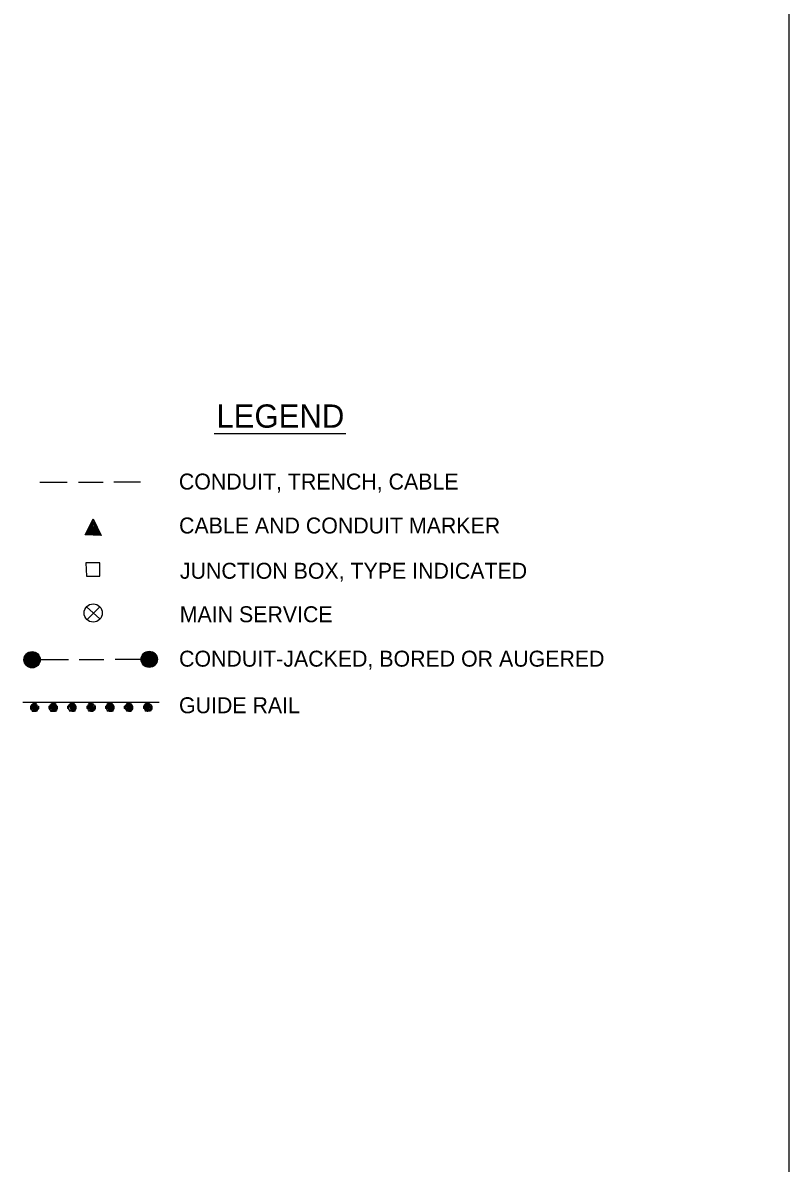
# Model space of a CAD drawing. Extents: x 36 to 2622, y -5330 to 219.
# Drawn here: x 717.9 to 861.9, y -5154 to -4939.9 of the extents above; entities that cross this region are included whole.
import ezdxf

# ---------------------------------------------------------------- set-up
doc = ezdxf.new("R2010")
doc.units = 0
doc.layers.add('1', color=7, linetype='Continuous')
doc.layers.add('2', color=7, linetype='Continuous')

msp = doc.modelspace()

# ---------------------------------------------------------------- linework, layer by layer
at = {"layer": '1'}
msp.add_line((861.86, -5314.83), (861.86, -4750.83), dxfattribs=at)
at = {"layer": '2'}
for p, q in [((753.84, -5017), (778.59, -5017)), ((721.13, -5026.13), (726.25, -5026.13)), ((728.38, -5026.13), (733, -5026.13)), ((740, -5026.13), (735, -5026.13)), ((729.63, -5036), (731.13, -5033)), ((729.75, -5036), (731.13, -5033.25)), ((729.88, -5035.88), (731.13, -5033.5)), ((731.13, -5033), (732.63, -5036.13)), ((731.13, -5033.25), (732.5, -5036)), ((731.13, -5033.5), (732.38, -5035.88)), ((730.13, -5035.75), (731.13, -5033.63)), ((730.25, -5035.63), (731.13, -5033.88)), ((731.88, -5035.63), (730.25, -5035.63)), ((730.38, -5035.38), (731.13, -5034.25)), ((731.75, -5035.38), (730.38, -5035.38)), ((730.5, -5035.38), (731.13, -5034.5)), ((731.5, -5035.38), (730.5, -5035.38)), ((730.88, -5035.25), (731.13, -5034.63)), ((731.38, -5035.25), (730.88, -5035.25)), ((731, -5035.13), (731.13, -5034.88)), ((731.25, -5035.13), (731, -5035.13)), ((731.13, -5033.63), (732, -5035.75)), ((731.13, -5033.88), (731.88, -5035.63)), ((731.13, -5034.25), (731.75, -5035.38)), ((731.13, -5034.5), (731.5, -5035.38)), ((731.13, -5034.63), (731.38, -5035.25)), ((731.13, -5034.88), (731.25, -5035.13)), ((732.63, -5036.13), (729.63, -5036)), ((732.5, -5036), (729.75, -5036)), ((732.38, -5035.88), (729.88, -5035.88)), ((732, -5035.75), (730.13, -5035.75)), ((729.88, -5049.5), (732.38, -5051.75)), ((732.38, -5049.5), (730, -5051.88)), ((721.25, -5059.38), (726.5, -5059.38)), ((728.5, -5059.38), (733.13, -5059.38)), ((740.13, -5059.38), (735.25, -5059.38)), ((717.91, -5067.45), (743.52, -5067.45)), ((720.14, -5068.2), (720.14, -5068.2)), ((723.64, -5068.2), (723.64, -5068.2)), ((727.26, -5068.2), (727.26, -5068.2)), ((730.76, -5068.2), (730.76, -5068.2)), ((734.39, -5068.2), (734.39, -5068.2)), ((737.89, -5068.2), (737.89, -5068.2)), ((741.39, -5068.2), (741.39, -5068.2))]:
    msp.add_line(p, q, dxfattribs=at)
msp.add_lwpolyline([(729.88, -5043.75), (732.38, -5043.75), (732.38, -5041.25), (729.75, -5041.25)], close=True, dxfattribs=at)
for points in [[(720.14, -5068.45), (720.01, -5068.45), (720.01, -5068.45), (720.14, -5068.2), (720.26, -5068.45), (720.14, -5068.58), (720.01, -5068.7), (719.89, -5068.58), (719.89, -5068.45), (719.89, -5068.2), (720.01, -5068.08), (720.26, -5068.08), (720.39, -5068.45), (720.39, -5068.58), (720.14, -5068.83), (719.89, -5068.7), (719.76, -5068.58), (719.76, -5068.2), (719.89, -5067.95), (720.26, -5067.95), (720.39, -5068.08), (720.51, -5068.45), (720.51, -5068.7), (720.26, -5068.83), (720.14, -5068.95), (719.89, -5068.95), (719.64, -5068.83), (719.51, -5068.58), (719.64, -5068.2), (719.76, -5067.95), (720.01, -5067.83), (720.39, -5067.83), (720.51, -5068.08), (720.64, -5068.45), (720.64, -5068.7), (720.51, -5068.95), (720.26, -5069.08), (720.01, -5069.08), (719.76, -5069.08), (719.64, -5068.95), (719.51, -5068.83), (719.39, -5068.58), (719.39, -5068.2), (719.51, -5068.08), (719.64, -5067.83), (719.89, -5067.7), (720.01, -5067.7), (720.26, -5067.7), (720.39, -5067.7), (720.51, -5067.83), (720.64, -5068.08), (720.89, -5068.2), (720.89, -5068.58), (720.89, -5068.7), (720.64, -5068.95), (720.51, -5069.08), (720.39, -5069.2), (720.14, -5069.2), (720.01, -5069.2), (719.76, -5069.2), (719.64, -5069.08)], [(723.64, -5068.45), (723.51, -5068.45), (723.51, -5068.45), (723.64, -5068.2), (723.89, -5068.45), (723.64, -5068.58), (723.51, -5068.7), (723.39, -5068.58), (723.39, -5068.45), (723.39, -5068.2), (723.51, -5068.08), (723.89, -5068.08), (724.01, -5068.45), (724.01, -5068.58), (723.64, -5068.83), (723.39, -5068.7), (723.26, -5068.58), (723.26, -5068.2), (723.39, -5067.95), (723.89, -5067.95), (724.01, -5068.08), (724.14, -5068.45), (724.14, -5068.7), (723.89, -5068.83), (723.64, -5068.95), (723.39, -5068.95), (723.14, -5068.83), (723.01, -5068.58), (723.14, -5068.2), (723.26, -5067.95), (723.51, -5067.83), (724.01, -5067.83), (724.14, -5068.08), (724.26, -5068.45), (724.26, -5068.7), (724.14, -5068.95), (723.89, -5069.08), (723.51, -5069.08), (723.26, -5069.08), (723.14, -5068.95), (723.01, -5068.83), (722.89, -5068.58), (722.89, -5068.2), (723.01, -5068.08), (723.14, -5067.83), (723.39, -5067.7), (723.51, -5067.7), (723.89, -5067.7), (724.01, -5067.7), (724.14, -5067.83), (724.26, -5068.08), (724.39, -5068.2), (724.39, -5068.58), (724.39, -5068.7), (724.26, -5068.95), (724.14, -5069.08), (724.01, -5069.2), (723.64, -5069.2), (723.51, -5069.2), (723.26, -5069.2), (723.14, -5069.08)], [(727.26, -5068.45), (727.14, -5068.45), (727.14, -5068.2), (727.26, -5068.2), (727.39, -5068.45), (727.26, -5068.58), (727.14, -5068.7), (727.01, -5068.58), (727.01, -5068.45), (727.01, -5068.2), (727.14, -5068.08), (727.39, -5068.08), (727.51, -5068.45), (727.51, -5068.58), (727.26, -5068.83), (727.01, -5068.7), (726.89, -5068.58), (726.89, -5068.2), (727.01, -5067.95), (727.39, -5067.95), (727.51, -5068.08), (727.64, -5068.45), (727.64, -5068.7), (727.39, -5068.83), (727.26, -5068.95), (727.01, -5068.95), (726.64, -5068.83), (726.51, -5068.58), (726.64, -5068.2), (726.89, -5067.95), (727.14, -5067.83), (727.51, -5067.83), (727.64, -5068.08), (727.76, -5068.2), (727.76, -5068.7), (727.64, -5068.95), (727.39, -5069.08), (727.14, -5069.08), (726.89, -5069.08), (726.64, -5068.95), (726.51, -5068.7), (726.39, -5068.58), (726.39, -5068.2), (726.51, -5068.08), (726.64, -5067.83), (726.89, -5067.7), (727.14, -5067.7), (727.39, -5067.7), (727.51, -5067.7), (727.64, -5067.83), (727.76, -5067.95), (727.89, -5068.2), (727.89, -5068.58), (727.89, -5068.7), (727.76, -5068.95), (727.64, -5069.08), (727.51, -5069.2), (727.26, -5069.2), (727.14, -5069.2), (726.89, -5069.08), (726.64, -5069.08)], [(730.76, -5068.45), (730.64, -5068.45), (730.64, -5068.2), (730.76, -5068.2), (730.89, -5068.45), (730.76, -5068.58), (730.64, -5068.7), (730.51, -5068.58), (730.51, -5068.45), (730.51, -5068.2), (730.64, -5068.08), (730.89, -5068.08), (731.01, -5068.45), (731.01, -5068.58), (730.76, -5068.83), (730.51, -5068.7), (730.39, -5068.58), (730.39, -5068.2), (730.51, -5067.95), (730.89, -5067.95), (731.01, -5068.08), (731.14, -5068.45), (731.14, -5068.7), (730.89, -5068.83), (730.76, -5068.95), (730.51, -5068.95), (730.26, -5068.83), (730.14, -5068.58), (730.26, -5068.2), (730.39, -5067.95), (730.64, -5067.83), (731.01, -5067.83), (731.14, -5068.08), (731.39, -5068.2), (731.39, -5068.7), (731.14, -5068.95), (730.89, -5069.08), (730.64, -5069.08), (730.39, -5069.08), (730.26, -5068.95), (730.14, -5068.7), (730.01, -5068.58), (730.01, -5068.2), (730.14, -5068.08), (730.26, -5067.83), (730.39, -5067.7), (730.64, -5067.7), (730.89, -5067.7), (731.01, -5067.7), (731.14, -5067.83), (731.39, -5067.95), (731.51, -5068.2), (731.51, -5068.58), (731.51, -5068.7), (731.39, -5068.95), (731.14, -5069.08), (731.01, -5069.2), (730.76, -5069.2), (730.64, -5069.2), (730.39, -5069.08), (730.26, -5069.08)], [(734.39, -5068.45), (734.14, -5068.45), (734.14, -5068.2), (734.39, -5068.2), (734.51, -5068.45), (734.39, -5068.58), (734.14, -5068.7), (734.01, -5068.58), (734.01, -5068.45), (734.01, -5068.2), (734.14, -5068.08), (734.51, -5068.08), (734.64, -5068.45), (734.51, -5068.58), (734.39, -5068.83), (734.01, -5068.7), (733.89, -5068.58), (733.89, -5068.08), (734.01, -5067.95), (734.51, -5067.95), (734.64, -5068.08), (734.76, -5068.45), (734.76, -5068.7), (734.51, -5068.83), (734.39, -5068.95), (734.01, -5068.95), (733.76, -5068.83), (733.64, -5068.58), (733.76, -5068.2), (733.89, -5067.95), (734.14, -5067.83), (734.64, -5067.83), (734.76, -5068.08), (734.89, -5068.2), (734.89, -5068.7), (734.76, -5068.95), (734.51, -5069.08), (734.14, -5069.08), (733.89, -5069.08), (733.76, -5068.95), (733.64, -5068.7), (733.51, -5068.58), (733.51, -5068.2), (733.64, -5068.08), (733.76, -5067.83), (733.89, -5067.7), (734.14, -5067.7), (734.51, -5067.7), (734.64, -5067.7), (734.76, -5067.83), (734.89, -5067.95), (735.01, -5068.2), (735.01, -5068.58), (735.01, -5068.7), (734.89, -5068.95), (734.76, -5069.08), (734.64, -5069.2), (734.39, -5069.2), (734.14, -5069.2), (733.89, -5069.08), (733.76, -5069.08)], [(737.89, -5068.45), (737.76, -5068.45), (737.76, -5068.2), (737.89, -5068.2), (738.01, -5068.45), (737.89, -5068.58), (737.76, -5068.58), (737.64, -5068.58), (737.64, -5068.45), (737.64, -5068.2), (737.76, -5068.08), (738.01, -5068.08), (738.14, -5068.45), (738.01, -5068.58), (737.89, -5068.83), (737.64, -5068.7), (737.51, -5068.58), (737.51, -5068.08), (737.64, -5067.95), (738.01, -5067.95), (738.14, -5068.08), (738.26, -5068.45), (738.26, -5068.7), (738.01, -5068.83), (737.89, -5068.95), (737.64, -5068.95), (737.39, -5068.7), (737.14, -5068.45), (737.39, -5068.2), (737.51, -5067.95), (737.76, -5067.83), (738.14, -5067.83), (738.26, -5068.08), (738.39, -5068.2), (738.39, -5068.7), (738.26, -5068.95), (738.01, -5069.08), (737.76, -5069.08), (737.51, -5069.08), (737.39, -5068.95), (737.14, -5068.7), (737.01, -5068.58), (737.01, -5068.2), (737.14, -5068.08), (737.39, -5067.83), (737.51, -5067.7), (737.76, -5067.7), (738.01, -5067.7), (738.14, -5067.7), (738.26, -5067.83), (738.39, -5067.95), (738.51, -5068.2), (738.51, -5068.58), (738.51, -5068.7), (738.39, -5068.83), (738.26, -5069.08), (738.14, -5069.2), (737.89, -5069.2), (737.76, -5069.2), (737.51, -5069.08), (737.39, -5069.08)], [(741.39, -5068.45), (741.26, -5068.45), (741.26, -5068.2), (741.39, -5068.2), (741.51, -5068.45), (741.39, -5068.58), (741.26, -5068.58), (741.14, -5068.58), (741.01, -5068.45), (741.14, -5068.2), (741.26, -5068.08), (741.51, -5068.08), (741.64, -5068.45), (741.51, -5068.58), (741.39, -5068.83), (741.14, -5068.7), (741.01, -5068.58), (741.01, -5068.08), (741.14, -5067.95), (741.51, -5067.95), (741.64, -5068.08), (741.89, -5068.45), (741.89, -5068.7), (741.51, -5068.83), (741.39, -5068.95), (741.14, -5068.95), (740.89, -5068.7), (740.76, -5068.45), (740.89, -5068.2), (741.01, -5067.95), (741.26, -5067.83), (741.64, -5067.83), (741.89, -5067.95), (742.01, -5068.2), (742.01, -5068.7), (741.89, -5068.95), (741.51, -5069.08), (741.26, -5069.08), (741.01, -5069.08), (740.89, -5068.95), (740.76, -5068.7), (740.64, -5068.58), (740.64, -5068.2), (740.76, -5067.95), (740.89, -5067.83), (741.01, -5067.7), (741.26, -5067.7), (741.51, -5067.7), (741.64, -5067.7), (741.89, -5067.83), (742.01, -5067.95), (742.14, -5068.2), (742.14, -5068.58), (742.14, -5068.7), (742.01, -5068.83), (741.89, -5069.08), (741.64, -5069.08), (741.39, -5069.2), (741.26, -5069.2), (741.01, -5069.08), (740.89, -5069.08)]]:
    msp.add_lwpolyline(points, dxfattribs=at)
for centre, radius in [((731.13, -5050.68), 1.7), ((719.66, -5059.45), 1.53), ((719.66, -5059.45), 1.42), ((719.66, -5059.45), 1.31), ((719.66, -5059.45), 1.21), ((719.66, -5059.45), 1.1), ((719.66, -5059.45), 0.988), ((719.66, -5059.45), 0.88), ((719.66, -5059.45), 0.771), ((719.66, -5059.45), 0.662), ((719.66, -5059.45), 0.553), ((719.66, -5059.45), 0.444), ((719.66, -5059.45), 0.335), ((719.66, -5059.45), 0.226), ((741.65, -5059.38), 1.53), ((741.65, -5059.38), 1.42), ((741.65, -5059.38), 1.31), ((741.65, -5059.38), 1.21), ((741.65, -5059.38), 1.1), ((741.65, -5059.38), 0.988), ((741.65, -5059.38), 0.88), ((741.65, -5059.38), 0.771), ((741.65, -5059.38), 0.662), ((741.65, -5059.38), 0.553), ((741.65, -5059.38), 0.444), ((741.65, -5059.38), 0.335), ((741.65, -5059.38), 0.226), ((741.65, -5059.38), 0.118), ((719.66, -5059.45), 0.118)]:
    msp.add_circle(centre, radius, dxfattribs=at)

# ---------------------------------------------------------------- texts
for s, height, p in [('LEGEND', 4.37, (754.27, -5015.89)), ('CONDUIT, TRENCH, CABLE', 2.9955, (747.23, -5027.5)), ('CABLE AND CONDUIT MARKER', 2.9955, (747.26, -5035.75)), ('JUNCTION BOX, TYPE INDICATED', 2.9955, (747.42, -5044.25)), ('MAIN SERVICE', 2.9955, (747.39, -5052.41)), ('CONDUIT-JACKED, BORED OR AUGERED', 2.9955, (747.26, -5060.75)), ('GUIDE RAIL', 2.996, (747.25, -5069.5))]:
    msp.add_text(s, height=height, dxfattribs=at).set_placement(p)

doc.saveas('drawing.dxf')
